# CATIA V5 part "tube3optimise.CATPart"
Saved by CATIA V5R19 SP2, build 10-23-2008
Part number: tube3
Bounding box of the stored display mesh (mm): x -940 to 60, y 0 to 380, z -300 to 100
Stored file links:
  C:\Users\marc\Desktop\boulot\Semestre 3\IAO\Projet2\tube3optimise.CATPart
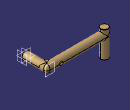
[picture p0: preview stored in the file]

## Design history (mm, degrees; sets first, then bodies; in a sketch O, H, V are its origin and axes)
Parameters
  raytube = 60 mm
  longtube1 = 320 mm
  longtube2 = 1000 mm
  longtube3 = 300 mm
Body1 (main body)
  Sketch1 on zx-plane, origin (0, 0, 0), H (-1, 0, 0), V (0, 0, 1)
    circle A1 centre (0, 0) radius 60
    point P1 (60, 0)
    radius A1 = 60 {= raytube}
    coincidence: A1 P1, P1 H
  Pad1: profile Sketch1, direction (0, 1, 0), length 380 {= raytube +longtube1}
  Plane1: type Offset, RefPlane yz-plane, Offset 60 {= raytube}
  Body2
    Sketch2 on Plane1, origin (60, 0, 0), H (0, 1, 0), V (0, 0, 1)
      circle A1 centre (320, 0) radius 60
      point P1 (320, 0)
      reference projected line E1 (0, 60) -> (0, -60) from edge [start face of Pad1 | face of Pad1 from Sketch1.A1]
      radius A1 = 60 {= raytube}
      distance P1 E1 = 320 {= longtube1}
      coincidence: P1 H
    Pad2: profile Sketch2, direction (-1, 0, 0), length 1000 {= longtube2}
  Trim1: tool Body2, faces to remove start face of Pad2; end face of Pad1
  Body3
    Sketch3 on xy-plane, origin (0, 0, 0), H (1, 0, 0), V (0, 1, 0)
      circle A1 centre (-880, 320) radius 60
      point P1 (-880, 320)
      reference intersected line E1 through (0, 0) direction (0, 1) from yz-plane
      reference projected line E2 through (0, 320) direction (1, 0) from axis of face of Pad2 from Sketch2.A1
      radius A1 = 60 {= raytube}
      distance E1 P1 = 880 {= longtube2 -2*raytube}
      distance E2 P1 = 0
    Pad3: profile Sketch3, direction (0, 0, 1), length 300 {= longtube3}, mirrored extent
  Trim2: tool Body3, faces to remove end face of Pad2
  Body4
    Plane2: type Offset, RefPlane zx-plane, Offset 365 {= longtube1 +0.75*raytube}
    Sketch4 on Plane2, origin (0, 365, 0), H (-1, 0, 0), V (0, 0, 1)
      line L1 (133.3333, 0) -> (193.3333, 0)
      point P1 (133.3333, 0)
      arc A1 centre (163.3333, 0) radius 30 from (133.3333, 0) to (193.3333, 0) cw
      distance O P1 = 133.3333 {= longtube2 /7.5}
      length L1 = 60 {= raytube}
      radius A1 = 30 {= raytube /2}
      coincidence: P1 H
      horizontal: L1 H
    Shaft1: profile Sketch4, axis Sketch4.L1, angle 360
  Remove1: tool Body4
  Body5
    Sketch5 on end face of Pad3, origin (0, 0, 300), H (1, 0, 0), V (0, 1, 0)
      circle A1 centre (-880, 320) radius 60
      reference projected circle E1 centre (-880, 320) radius 60 from edge [face of Pad3 from Sketch3.A1 | end face of Pad3]
      radius A1 = 60 {= raytube}
      concentricity: A1 E1
    Pad4: profile Sketch5, direction (0, 0, -1), length 200 {= longtube3 /1.5}
  Remove2: tool Body5
  Chamfer1: length 4, angle 45, on end face of Pad4
  Fillet1: radius 50, on edge [face of Pad1 | face of Pad2 from Sketch2.A1]
Relations
  Plane2.Offset = longtube1 +2raytube /3 (deactivated)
